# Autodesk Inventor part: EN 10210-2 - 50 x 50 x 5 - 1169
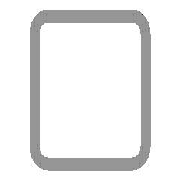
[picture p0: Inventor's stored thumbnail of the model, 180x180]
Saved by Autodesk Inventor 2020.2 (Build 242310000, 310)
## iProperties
IsCustomPart: 1
Created: 2019-01
Part Number: EN 10210-2 - 50 x 50 x 5 - 1169
Material: Stahl, weich
Description: Rohrleitung
Document SubType Name: Modeling
Standard: DIN
Designer: lutzd
Standard Revision: 2006-07
Standards Organization: DIN
Language: de-DE
Size Designation: 50 x 50 x 5
Categories: <MemberInstance><Categories><Category DisplayName="Profile" InternalName="089c4875-fa83-4c05-b084-43b9cc11f5ed" Mnemonic="GRDR"><CategoryParameter DisplayName="
Stock Number: 50 x 50 x 5
Mass: 8010.1 g
Surface Area: 3975.69 cm^2
Volume: 1020.39 cm^3
Density: 7.85 g/cm^3
Appearance: Semi-Polished(8)
G_L: 1169,000 mm
G_W: 50,000 mm
G_H: 50,000 mm
DocNumber: ADSK-014272
Folder: .
Dimensions: 50x50x1169 mm
Mass: 8,01 kg
+67763BF9-9DDF-427F-9EB1-5BB07833E6D5+SCHNITTDETAIL1: Schnittwinkel 90,00 grd
VLT_Material: Stahl, weich
_CCFamilyMember: 16
_CCFamilyDisplayName: DIN EN 10210-2 (USAS B17.1 quadratisch) - Rohrleitung — In Klammern angegebene Größen wurden aufgehoben
_FrameMemberDoc: Frame Member File
_Version: 15.0.0
_GetPNFromCC: 1
Title: Profil-Bauteil
Author: lutzd
Revision Number: -
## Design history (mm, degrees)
node "Startebene"
node "Endebene"
sketch "Skizze"
  geometry: L1 (-25, -17.5)-(-25, 17.5); L2 (-17.5, 25)-(17.5, 25); L3 (25, 17.5)-(25, -17.5); L4 (17.5, -25)-(-17.5, -25); L5 (-15, 20)-(15, 20); L6 (20, 15)-(20, -15); L7 (15, -20)-(-15, -20); L8 (-20, -15)-(-20, 15); L9 (0, 37.175)-(0, -37.175) reference; L10 (-37.175, 0)-(37.175, 0) reference; A1 r 7.5 centre (-17.5, -17.5) between (-25, -17.5) and (-17.5, -25); A2 r 7.5 centre (-17.5, 17.5) between (-17.5, 25) and (-25, 17.5); A3 r 7.5 centre (17.5, 17.5) between (25, 17.5) and (17.5, 25); A4 r 7.5 centre (17.5, -17.5) between (17.5, -25) and (25, -17.5); A5 r 5 centre (-15, -15) between (-20, -15) and (-15, -20); A6 r 5 centre (-15, 15) between (-15, 20) and (-20, 15); A7 r 5 centre (15, 15) between (20, 15) and (15, 20); A8 r 5 centre (15, -15) between (15, -20) and (20, -15)
  constraints: 16 end point, 16 point on circle, 16 tangent, 8 centre point, 6 equal radius, 4 parallel, 2 perpendicular, 2 other
  dimensions: "d7" = 7.5 radius of A1 (= G_IR); "d10" = 50 distance between parallel lines of L2 L4 (= G_H); "d11" = 50 distance between parallel lines of L1 L3 (= G_W); "d12" = 5 distance between parallel lines of L3 L6 (= G_T); "d15" = 25 distance between parallel lines of L2 L10 (= 0.5 x d10); "d16" = 25 distance between parallel lines of L9 L3 (= 0.5 x d11); "d19" = 5 radius of A5 (= G_T); "d20" = 5 distance between parallel lines of L4 L7 (= G_T)
extrude "Körper" new body sketch "Skizze" stored distance "d3" = 1169 (= G_L); taper "d4" = 0 deg
node "Driven Length"
  sketch "Sketch3"
    geometry: L1 (0, 0)-(10, 0) reference
    constraints: 2 end point, 1 horizontal
  workplane "Work Plane3"
  sketch "Sketch4"
    geometry: L1 (-2, 0)-(12, 0) reference; L2 (-2, 1169)-(12, 1169) reference
    dimensions: "d18" = 1169 distance between parallel lines of L1 L2 (derived)
workplane "Arbeitsebene4"
feature "Trennen1"
sketch "Skizze5"
  geometry: L1 (-35, 0)-(0, 0) reference; L2 (-17.5, 0)-(-17.5, 630.5); 3 further points
  constraints: 2 end point, 1 coincident, 1 midpoint, 1 point on line, 1 vertical
  dimensions: "d21" = 153 distance of point (-17.5, 477.5) point (-17.5, 630.5); "d22" = 477.5 distance from line of L1 point (-17.5, 477.5)
hole "Bohrung1" sketch "Skizze5" at (-17.5, 630.5), (-17.5, 477.5) diameter "d23" = 6.647; stored, may be unused: countersink angle "d27" = 90 deg, drill point angle "d29" = 118 deg; dims "d24" = 16, "d25" = 17.3, "d26" = 2, "d28" = 22.2
body "Solid1"
other parameters: "G_W" = 50 [user parameter; used in 1 equation term], "G_H" = 50 [user parameter; used in 1 equation term], "G_T" = 5 [user parameter; used in 3 equation terms], "G_IR" = 7.5 [user parameter; used in 1 equation term], "G_L" = 1169 (= d18) [user parameter; used in 1 equation term], "G_OFFSET_START" = 0 [user parameter; used in 1 equation term], "G_OFFSET_END" = -25 [user parameter; used in 1 equation term], "d13" = 0 (computed from G_OFFSET_START), "d14" = 1169 (= G_OFFSET_END + B_L), "B_L" = 1194 [user parameter; used in 1 equation term], "d17" = 90 deg
